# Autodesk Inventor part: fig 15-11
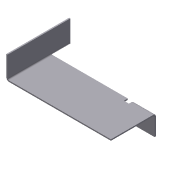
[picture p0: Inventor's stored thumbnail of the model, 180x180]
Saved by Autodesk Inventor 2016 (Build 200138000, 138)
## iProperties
Shininess: 77.0
Angle Display Precision: 2
Document Length Units: 11269
Document Angle Units: 11279
Document Time Units: 11290
Document Mass Units: 11283
Document Length Units Precision: 3
Document Angle Units Precision: 2
Created: 2002-04
Part Number: fig 15-11
Material: Aluminum-6061
Document SubType Name: Sheet Metal
Density: 1 g/cm^3
Sheet Metal Rule: Default
Appearance: Aluminum - Flat-1
Density: 0.0
Volumn: 0.0
Area: 0.0
PropertySet Name: Model Information
Control State: 0
Master: False
Checked Out: False
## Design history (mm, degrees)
node "Face1"
  sketch "Sketch1"
    geometry: L1 (-49.559, 19.574)-(-49.559, -30.426); L2 (-49.559, -30.426)-(50.441, -30.426); L3 (50.441, -30.426)-(50.441, 19.574); L4 (50.441, 19.574)-(32.941, 19.574); L5 (32.941, 19.574)-(32.941, 4.574); L6 (32.941, 4.574)-(-32.059, 4.574); L7 (-32.059, 4.574)-(-32.059, 19.574); L8 (-32.059, 19.574)-(-49.559, 19.574)
    constraints: 16 end point, 6 parallel, 2 equal length, 1 perpendicular, 1 vertical
    dimensions: "d0" = 100 distance of L1.end L2.end; "d1" = 65 distance of L5.end L6.end; "d2" = 15 distance of L6.end L7.end; "d3" = 50 distance of L1.start L1.end
sketch "Sketch2"
  geometry: L1 (100, 0)-(0, 0) reference; L2 (17.5, 50)-(17.5, 35) reference; L3 (82.5, 50)-(82.5, 0)
  constraints: 2 end point, 1 parallel, 1 point on line
sketch "Sketch3"
  geometry: L1 (81.369, -50)-(0, -50) reference; L2 (17.5, 0)-(17.5, -50)
  constraints: 2 end point, 1 perpendicular, 1 point on line
feature "Fold2" sketch "Sketch3" dims "d8" = 1 (= BendRadius), "d9" = 90 deg, "d10" = 1 (= BendRadius), "d14" = 1 (= BendReliefWidth), "d15" = 0.5 (= BendReliefDepth), "d16" = 2 (= MinimumRemnant), "SeamGap" = 0.01, "Thickness" = 1
sketch "Sketch4"
  geometry: L1 (17.5, 0)-(17.5, -50) reference; L2 (-63.869, -15)-(0, -15) reference; L3 (0, -15)-(17.5, -15)
  constraints: 2 end point, 1 collinear, 1 point on line
feature "Fold3" sketch "Sketch4" dims "d11" = 1 (= BendRadius), "d12" = 90 deg, "d13" = 1 (= BendRadius), "d17" = 4, "d18" = 2, "d19" = 2 (= MinimumRemnant), "SeamGap" = 0.01, "Thickness" = 1
body "Solid1"
face "Plate1" dims "Thickness" = 1
other parameters: "BendRadius" = 1 (= Thickness), "BendReliefWidth" = 1 (= Thickness), "BendReliefDepth" = 0.5 (= 0.5 x Thickness), "CornerReliefSize" = 4 (= 4 x Thickness), "MinimumRemnant" = 2 (= 2 x Thickness), "TransitionRadius" = 1 (= BendRadius), "d4" = 1 (= BendRadius), "JacobiRadiusSize" = 1 (= Thickness), "GapSize" = 1 (= Thickness)
